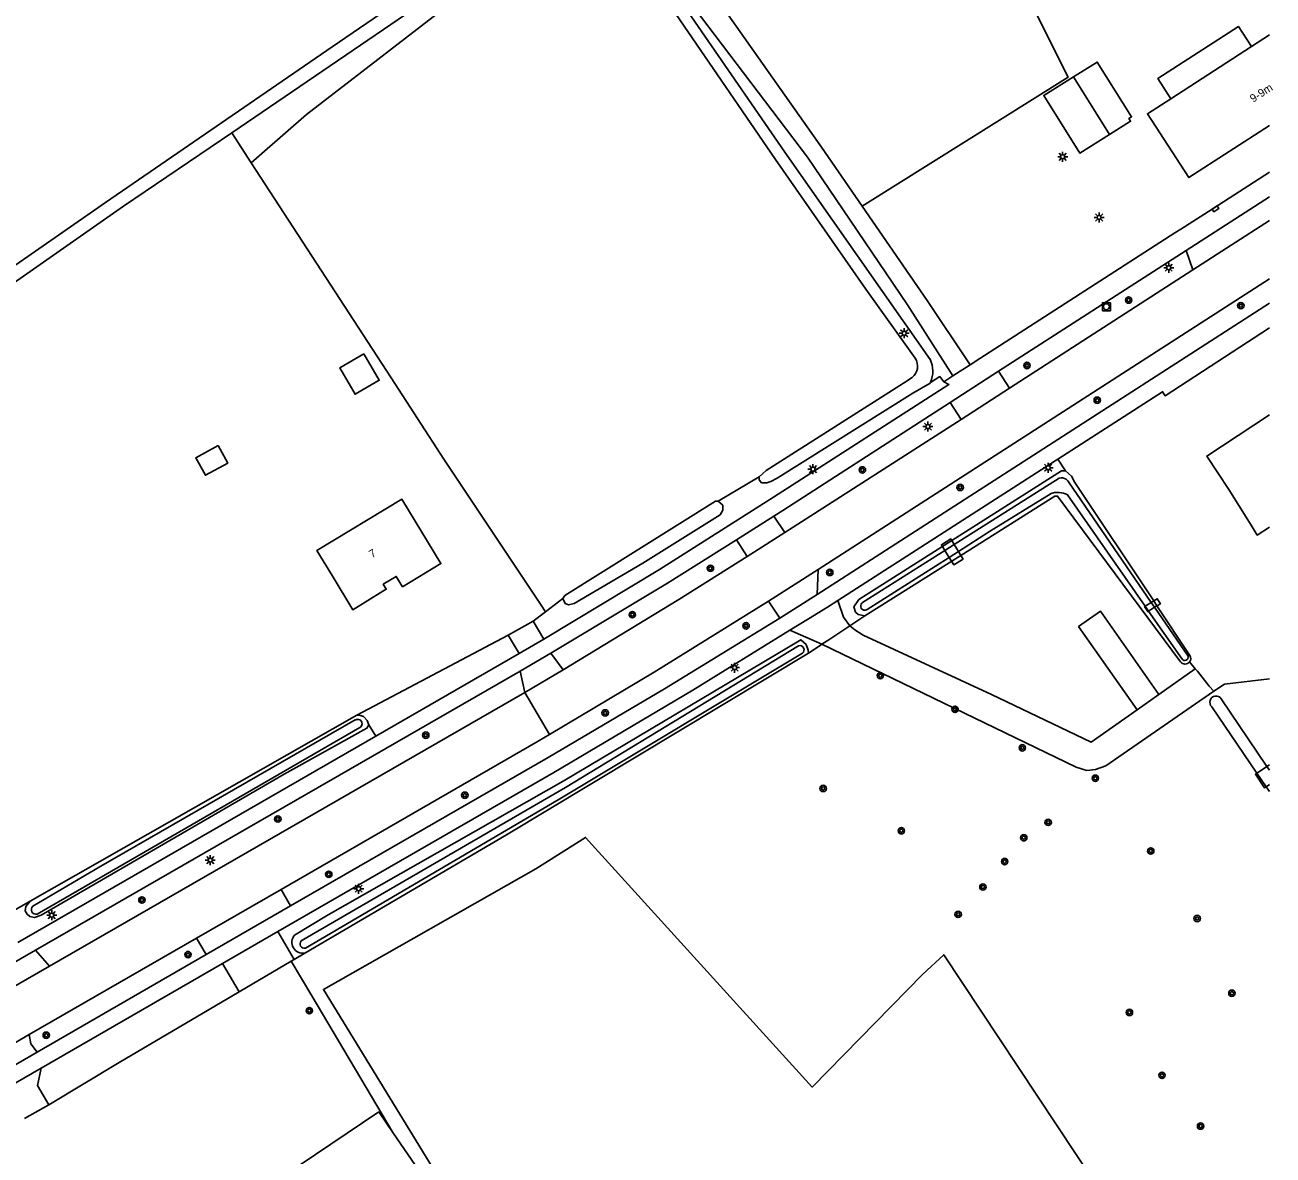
# Model space of a CAD drawing. Extents: x 137000 to 140001, y 403500 to 406000.
# Drawn here: x 139844.4 to 140000.4, y 404057.8 to 404199.1 of the extents above; entities that cross this region are included whole.
import ezdxf

# ---------------------------------------------------------------- set-up
doc = ezdxf.new("R2010")
doc.units = 0
for name, color, linetype in [('gg-afsc-erfafscheiding', 7, 'Continuous'), ('gg-afsc-hekwerk', 7, 'Continuous'), ('gg-anno-huisnummerreeks BGT', 7, 'Continuous'), ('gg-bbg-bijgebouw', 7, 'Continuous'), ('gg-bbg-hoofdgebouw', 7, 'Continuous'), ('gg-bbg-luifel en loopbrug', 7, 'Continuous'), ('gg-bbg-overig bouwwerk', 7, 'Continuous'), ('gg-knt-bronhoudergrens', 7, 'Continuous'), ('gg-knt-verharding', 7, 'Continuous'), ('gg-knt-verharding nz', 7, 'Continuous'), ('gg-kntw-bovenkant insteek waterloop', 7, 'Continuous'), ('gg-kntw-waterlijn', 7, 'Continuous'), ('gg-kwrk-kunstwerk niveau 01', 7, 'Continuous'), ('gt-grn-groengrens', 7, 'Continuous'), ('gt-grn-weggrens', 7, 'Continuous'), ('gt-symb-boom', 7, 'Continuous'), ('gt-symb-kolk', 7, 'Continuous'), ('gt-symb-lichtmast', 7, 'Continuous'), ('gt-symb-rioolschacht', 7, 'Continuous')]:
    doc.layers.add(name, color=color, linetype=linetype)

# ---------------------------------------------------------------- blocks, each defined once
blk = doc.blocks.new('gt0-BOOM')
at = {"layer": 'gt-symb-boom'}
for radius in [0.4, 0.2]:
    blk.add_circle((0, 0), radius, dxfattribs=at)
blk = doc.blocks.new('gt0-LMAST')
at = {"layer": 'gt-symb-lichtmast'}
for p, q in [((-0.18, 0.17), (-0.45, 0.44)), ((-0.01, 0.25), (-0.01, 0.62)), ((0.17, 0.17), (0.44, 0.44)), ((-0.26, 0), (-0.63, 0)), ((-0.18, -0.18), (-0.45, -0.45)), ((-0.01, -0.25), (-0.01, -0.63)), ((0.44, -0.45), (0.17, -0.18)), ((0.24, 0), (0.62, 0))]:
    blk.add_line(p, q, dxfattribs=at)
blk.add_circle((-0.01, 0), 0.25, dxfattribs=at)
blk = doc.blocks.new('gt0-RS')
at = {"layer": 'gt-symb-rioolschacht'}
blk.add_lwpolyline([(-0.5, -0.5), (0.5, -0.5), (0.5, 0.5), (-0.5, 0.5)], close=True, dxfattribs=at)
blk.add_circle((0, 0), 0.375, dxfattribs=at)
blk = doc.blocks.new('gt0-KOLK')
at = {"layer": 'gt-symb-kolk'}
blk.add_lwpolyline([(0, 0), (0.37, 0), (0.37, 0.4), (-0.38, 0.4), (-0.38, 0), (0, 0)], dxfattribs=at)

msp = doc.modelspace()

# ---------------------------------------------------------------- linework, layer by layer
at = {"layer": 'gg-afsc-erfafscheiding'}
for p, q in [((139870.28, 404185.61), (139872.71, 404181.86)), ((139973.54, 404144.82), (139974.5, 404143.33)), ((139985.52, 404127.09), (139985.93, 404126.47)), ((139985.93, 404126.47), (139990.05, 404120.27)), ((139907.98, 404124.53), (139909.49, 404125.71)), ((139885.94, 404112.81), (139904.84, 404122.82)), ((139845.1, 404089.56), (139885.94, 404112.81)), ((139841.07, 404087.26), (139845.1, 404089.56))]:
    msp.add_line(p, q, dxfattribs=at)
for points in [[(139974.5, 404143.33), (139975.26, 404142.69), (139975.67, 404141.9), (139985.52, 404127.09)], [(139877.72, 404082.05), (139880.3, 404077.7), (139890.43, 404060.62)]]:
    msp.add_lwpolyline(points, dxfattribs=at)
msp.add_arc((139989.44, 404119.9), 0.72, 321.2636, 31.3937, dxfattribs=at)
at = {"layer": 'gg-afsc-hekwerk'}
for p, q in [((139885.94, 404112.81), (139845.1, 404089.56)), ((139845.1, 404089.56), (139841.07, 404087.26)), ((139871.2, 404078.22), (139856.22, 404069.39)), ((139847.42, 404064.1), (139856.22, 404069.39))]:
    msp.add_line(p, q, dxfattribs=at)
at = {"layer": 'gg-bbg-bijgebouw'}
msp.add_line((139890.43, 404060.62), (139888.66, 404063.2), dxfattribs=at)
for points in [[(139888.66, 404063.2), (139860.82, 404044.45), (139872, 404028.17), (139898.92, 404046.3)], [(139898.92, 404046.3), (139899.84, 404046.92), (139890.43, 404060.62)]]:
    msp.add_lwpolyline(points, dxfattribs=at)
at = {"layer": 'gg-bbg-hoofdgebouw'}
for q in [(140000, 404197.85), (139987.65, 404189.86)]:
    msp.add_line((139997.73, 404196.38), q, dxfattribs=at)
for points in [[(139987.65, 404189.86), (139984.74, 404187.98), (139989.93, 404180), (140000, 404186.49)], [(140000, 404150.35), (139992.14, 404145.18), (139994.89, 404141), (139997.69, 404136.53), (139998.46, 404135.31), (140000, 404136.32)], [(139889.19, 404128.28), (139889.6, 404128.53), (139889.22, 404129.16), (139890.85, 404130.14), (139891.63, 404128.85), (139896.42, 404131.75), (139891.55, 404139.79), (139880.92, 404133.37), (139882.82, 404130.25), (139885.42, 404125.98), (139889.19, 404128.28)]]:
    msp.add_lwpolyline(points, dxfattribs=at)
at = {"layer": 'gg-bbg-luifel en loopbrug'}
msp.add_line((139979.98, 404185.38), (139975.49, 404192.58), dxfattribs=at)
for points in [[(139997.73, 404196.38), (139996.1, 404198.9), (139986.02, 404192.38), (139987.65, 404189.86)], [(139979.98, 404185.38), (139982.63, 404187.03), (139982.42, 404187.37), (139982.76, 404187.58), (139978.47, 404194.44), (139975.49, 404192.58)], [(139975.49, 404192.58), (139971.77, 404190.26), (139976.27, 404183.06), (139979.98, 404185.38)]]:
    msp.add_lwpolyline(points, dxfattribs=at)
at = {"layer": 'gg-bbg-overig bouwwerk'}
for points in [[(139886.81, 404157.95), (139883.79, 404156.2), (139885.7, 404152.91), (139888.72, 404154.66), (139886.81, 404157.95)], [(139868.59, 404146.51), (139865.79, 404144.98), (139866.99, 404142.78), (139869.79, 404144.31), (139868.59, 404146.51)]]:
    msp.add_lwpolyline(points, dxfattribs=at)
at = {"layer": 'gg-knt-bronhoudergrens'}
for points in [[(139949.08, 404176.44), (139974.82, 404192.53), (139967.8, 404206.65), (139975.35, 404211.27), (139975.52, 404212.67), (139977.9, 404214.5), (139981.43, 404217.7), (139983.63, 404220.66), (139984.38, 404222.22), (139987.69, 404224.46), (139993.63, 404227.8), (139995.73, 404224.77), (140000, 404226.86)], [(139908.29, 404093.58), (139914.51, 404097.52), (139942.82, 404066.32), (139956.67, 404080.42), (139959.27, 404082.86), (139970.91, 404065.29), (139993.05, 404031.94)], [(139932.29, 403995.97), (139881.75, 404078.52), (139908.29, 404093.58)]]:
    msp.add_lwpolyline(points, dxfattribs=at)
at = {"layer": 'gg-knt-verharding'}
for p, q in [((139989.58, 404170.9), (140000, 404177.61)), ((139989.58, 404170.9), (139966.14, 404155.79)), ((139990.43, 404168.46), (139989.58, 404170.9)), ((139990.43, 404168.46), (139967.51, 404153.68)), ((139943.59, 404131.02), (140000, 404167.36)), ((139943.45, 404127.88), (140000, 404164.32)), ((139962.57, 404156.59), (139960.43, 404155.22)), ((139959.27, 404154.47), (139960.43, 404155.22)), ((139960.09, 404151.88), (139966.14, 404155.79)), ((139966.14, 404155.79), (139967.51, 404153.68)), ((139961.45, 404149.77), (139960.09, 404151.88)), ((139938.05, 404137.69), (139933.36, 404134.73)), ((139939.43, 404135.63), (139938.05, 404137.69)), ((139934.72, 404132.65), (139933.36, 404134.73)), ((139943.59, 404131.02), (139943.45, 404127.88)), ((139938.78, 404124.94), (139943.45, 404127.88)), ((139937.38, 404127.05), (139938.78, 404124.94)), ((139904.84, 404122.82), (139907.98, 404124.53)), ((139907.98, 404124.53), (139909.3, 404122.31)), ((139944.04, 404121.66), (139940.04, 404123.41)), ((139904.84, 404122.82), (139906.19, 404120.5)), ((139906.19, 404120.5), (139909.3, 404122.31)), ((139888.29, 404110.18), (139906.19, 404120.5)), ((139910.17, 404120.54), (139906.33, 404118.3)), ((139911.7, 404118.47), (139910.17, 404120.54)), ((139990.72, 404118.6), (139986.17, 404115.4)), ((139990, 404119.45), (139990.72, 404118.6)), ((139845.77, 404083.43), (139906.33, 404118.3)), ((139906.9, 404115.64), (139906.33, 404118.3)), ((139906.9, 404115.64), (139847.49, 404081.43)), ((139986.17, 404115.4), (139983.44, 404113.48)), ((139888.29, 404110.18), (139843.56, 404084.39)), ((139865.9, 404084.93), (139876.46, 404091.02)), ((139876.46, 404091.02), (139877.65, 404088.96)), ((139867.1, 404082.87), (139877.65, 404088.96)), ((139876.04, 404085.75), (139869.12, 404081.77)), ((139878.08, 404082.27), (139876.04, 404085.75)), ((139844.98, 404072.87), (139865.9, 404084.93)), ((139865.9, 404084.93), (139867.1, 404082.87)), ((139845.77, 404083.43), (139836.05, 404077.83)), ((139847.49, 404081.43), (139845.77, 404083.43)), ((139845.95, 404070.67), (139867.1, 404082.87)), ((139869.12, 404081.77), (139846.46, 404068.69)), ((139869.12, 404081.77), (139871.2, 404078.22)), ((139871.2, 404078.22), (139877.72, 404082.05)), ((139840.31, 404067.41), (139845.95, 404070.67)), ((139846.46, 404068.69), (139841.28, 404065.7)), ((139847.42, 404064.1), (139844.4, 404062.39))]:
    msp.add_line(p, q, dxfattribs=at)
for points in [[(139909.49, 404125.71), (139908.95, 404126.57), (139896.79, 404144.8), (139890.2, 404154.98), (139872.71, 404181.86)], [(139962.57, 404156.59), (139963.79, 404157.38), (139988.18, 404173.08), (139988.92, 404173.55), (139992.35, 404175.76), (140000, 404180.68)], [(139949.08, 404176.44), (139957.22, 404164.65), (139962.57, 404156.59)], [(139973.54, 404144.82), (139986.63, 404153.23), (139986.95, 404152.73), (140000, 404161.2)], [(139959.27, 404154.47), (139959.92, 404154.14), (139938.01, 404140.03), (139923.76, 404131.01), (139909.3, 404122.31)], [(139938.05, 404137.69), (139939.17, 404138.39), (139960.09, 404151.88)], [(139939.43, 404135.63), (139940.46, 404136.28), (139961.45, 404149.77)], [(139973.54, 404144.82), (139973.2, 404144.6), (139946.04, 404127.14)], [(139933.36, 404134.73), (139924.76, 404129.31), (139910.17, 404120.54)], [(139934.72, 404132.65), (139926.16, 404127.24), (139911.7, 404118.47)], [(139910.02, 404110.4), (139923.07, 404118.18), (139937.38, 404127.05)], [(139940.04, 404123.41), (139942.39, 404124.86), (139944.76, 404126.32), (139946.04, 404127.14)], [(139947.54, 404123.97), (139946.76, 404125.07), (139946.04, 404127.14)], [(139877.65, 404088.96), (139909.82, 404107.52), (139924.38, 404116.11), (139938.78, 404124.94)], [(139986.17, 404115.4), (139978.87, 404125.79), (139976.13, 404123.87), (139983.44, 404113.48)], [(139940.04, 404123.41), (139927.91, 404115.93), (139910.53, 404105.65), (139876.04, 404085.75)], [(139944.04, 404121.66), (139945.02, 404122.3), (139947.54, 404123.97)], [(139947.54, 404123.97), (139948.17, 404123.46), (139949.19, 404122.78), (139965.24, 404115.39), (139977.7, 404109.44), (139983.44, 404113.48)], [(139993.03, 404115.82), (139981.18, 404107.59), (139979.54, 404106.47), (139978.25, 404106.02), (139977.17, 404105.89), (139975.82, 404106.32), (139944.04, 404121.66)], [(139990.72, 404118.6), (139990.98, 404118.3), (139992.47, 404116.41), (139993.03, 404115.82)], [(139993.03, 404115.82), (139994.36, 404116.67), (140000, 404117.35)], [(139876.46, 404091.02), (139908.6, 404109.55), (139910.02, 404110.4)], [(139877.72, 404082.05), (139878.08, 404082.26), (139878.08, 404082.27)], [(139845.95, 404070.67), (139845.18, 404071.72), (139844.98, 404072.87)], [(139846.46, 404068.69), (139846.01, 404066.51), (139847.42, 404064.1)]]:
    msp.add_lwpolyline(points, dxfattribs=at)
at = {"layer": 'gg-knt-verharding nz'}
for p, q in [((139990.43, 404168.46), (140000, 404174.63)), ((139967.51, 404153.68), (139961.45, 404149.77)), ((139934.72, 404132.65), (139939.43, 404135.63)), ((139937.38, 404127.05), (139943.59, 404131.02)), ((139911.7, 404118.47), (139906.9, 404115.64)), ((139847.49, 404081.43), (139837.32, 404075.57)), ((139844.98, 404072.87), (139838.86, 404069.34))]:
    msp.add_line(p, q, dxfattribs=at)
at = {"layer": 'gg-kntw-bovenkant insteek waterloop'}
for p, q in [((139960.59, 404134.12), (139959.43, 404133.39)), ((139959.95, 404132.52), (139961.11, 404133.26)), ((139984.45, 404126.43), (139984.87, 404125.82)), ((139985.63, 404126.28), (139985.21, 404126.9)), ((139992.77, 404113.83), (139998.43, 404105.54)), ((139993.96, 404114.86), (139999.68, 404106.38)), ((139845.96, 404087.93), (139886.3, 404111.24)), ((139999.68, 404106.38), (140000, 404105.91)), ((139998.43, 404105.54), (139999.58, 404103.85)), ((139999.58, 404103.85), (140000, 404103.24))]:
    msp.add_line(p, q, dxfattribs=at)
for points in [[(139777.24, 404123.6), (139796.02, 404136.4), (139822.77, 404154.86), (139854.51, 404176.9), (139882.82, 404196.33), (139904.39, 404211.07), (139912.76, 404216.98)], [(139957.59, 404157.27), (139939.42, 404183.18), (139926.09, 404202.55), (139915.74, 404217.27)], [(139870.28, 404185.61), (139906.27, 404210.13), (139912.64, 404214.82)], [(139915.67, 404214.61), (139922.12, 404205.83), (139938.26, 404182.24), (139949.55, 404166.06), (139955.71, 404157.42)], [(139778.07, 404121.99), (139799.67, 404136.56), (139827.67, 404156.11), (139856.76, 404176.41), (139870.28, 404185.61)], [(139955.32, 404155.01), (139954.25, 404154.31), (139937.1, 404143.39), (139936.21, 404142.61)], [(139936.21, 404142.61), (139936.21, 404142.21), (139936.5, 404141.84), (139937.15, 404141.83), (139937.66, 404142), (139938.46, 404142.43), (139955.42, 404153.03), (139957.56, 404154.28), (139957.62, 404154.4)], [(139960.59, 404134.12), (139973.72, 404142.44), (139973.94, 404142.47), (139974.17, 404142.45), (139974.38, 404142.39), (139974.58, 404142.28), (139974.75, 404142.14), (139974.89, 404141.96), (139985.21, 404126.9)], [(139961.11, 404133.26), (139965, 404135.74), (139972.71, 404140.51), (139973.14, 404140.62), (139973.42, 404140.65), (139973.7, 404140.64), (139973.97, 404140.61), (139974.24, 404140.56), (139974.51, 404140.47), (139974.76, 404140.36), (139984.45, 404126.43)], [(139911.65, 404127.4), (139911.93, 404127.77), (139930.77, 404139.57), (139931.1, 404139.56)], [(139911.65, 404127.4), (139911.98, 404126.75), (139912.36, 404126.58), (139913.1, 404126.74), (139921.65, 404131.8), (139931.34, 404137.86), (139931.67, 404138.43), (139931.65, 404139.04), (139931.1, 404139.56)], [(139959.43, 404133.39), (139949.12, 404126.87), (139949.04, 404126.79), (139948.94, 404126.66), (139948.9, 404126.5), (139948.9, 404126.34), (139948.96, 404126.18), (139949.05, 404126.06), (139949.06, 404126.05), (139949.2, 404125.96), (139949.3, 404125.92), (139949.47, 404125.91), (139949.63, 404125.95), (139949.72, 404126.01), (139959.95, 404132.52)], [(139984.87, 404125.82), (139989.06, 404119.8), (139989.15, 404119.71), (139989.27, 404119.65), (139989.41, 404119.63), (139989.58, 404119.67), (139989.73, 404119.78), (139989.8, 404119.9), (139989.83, 404120.03), (139989.82, 404120.16), (139985.63, 404126.28)], [(139942.36, 404120.55), (139942.33, 404120.93), (139942.09, 404121.62), (139941.4, 404122.23), (139911.72, 404104.53), (139882.35, 404087.84), (139878.15, 404085.31)], [(139879.44, 404083.06), (139904.63, 404097.85), (139942.36, 404120.55)], [(139845.41, 404088.91), (139853.94, 404093.93), (139885.72, 404112.2)]]:
    msp.add_lwpolyline(points, dxfattribs=at)
for centre, radius, start, end in [((139954.18, 404156.43), 1.82, 308.6086, 33.0069), ((139954.41, 404155.81), 3.5, 336.3307, 24.8264), ((139993.32, 404114.4), 0.788, 35.5911, 226.245), ((139886.02, 404111.72), 0.557, 300.9127, 121.9318), ((139845.82, 404088.5), 0.585, 135.0381, 283.5554), ((139879.18, 404084.4), 1.37, 138.8045, 280.8773)]:
    msp.add_arc(centre, radius, start, end, dxfattribs=at)
at = {"layer": 'gg-kntw-waterlijn'}
for points in [[(139941.14, 404121.48), (139912.02, 404103.76), (139878.97, 404084.58)], [(139941.62, 404120.53), (139911.07, 404102.23), (139879.49, 404083.68)]]:
    msp.add_lwpolyline(points, dxfattribs=at)
for centre, radius, start, end in [((139941.27, 404120.95), 0.549, 310.2963, 104.1278), ((139879.37, 404084.21), 0.546, 137.6685, 282.5038)]:
    msp.add_arc(centre, radius, start, end, dxfattribs=at)
at = {"layer": 'gg-kwrk-kunstwerk niveau 01'}
for p, q in [((139960.59, 404134.12), (139960.28, 404134.63)), ((139961.11, 404133.26), (139961.41, 404132.77)), ((139985.21, 404126.9), (139985.52, 404127.09)), ((139985.63, 404126.28), (139985.93, 404126.47)), ((139999.68, 404106.38), (140000, 404106.59)), ((139999.58, 404103.85), (140000, 404104.13))]:
    msp.add_line(p, q, dxfattribs=at)
for points in [[(139959.43, 404133.39), (139959.12, 404133.89), (139958.98, 404134.11), (139960.16, 404134.83), (139960.28, 404134.63)], [(139960.59, 404134.12), (139960.91, 404133.59), (139961.11, 404133.26)], [(139959.43, 404133.39), (139959.75, 404132.85), (139959.95, 404132.52)], [(139959.95, 404132.52), (139960.25, 404132.04), (139960.52, 404131.6), (139961.69, 404132.32), (139961.41, 404132.77)], [(139984.45, 404126.43), (139984.38, 404126.38), (139984.77, 404125.75), (139984.87, 404125.82)], [(139984.45, 404126.43), (139984.67, 404126.56), (139985.21, 404126.9)], [(139984.87, 404125.82), (139985.1, 404125.96), (139985.63, 404126.28)], [(139985.52, 404127.09), (139985.96, 404127.36), (139986.35, 404126.73), (139985.93, 404126.47)], [(139998.43, 404105.54), (139999.01, 404105.92), (139999.68, 404106.38)], [(139998.43, 404105.54), (139998.24, 404105.41), (139999.38, 404103.71), (139999.58, 404103.85)]]:
    msp.add_lwpolyline(points, dxfattribs=at)
at = {"layer": 'gt-grn-groengrens'}
for p, q in [((139931.1, 404139.56), (139936.21, 404142.61)), ((139949.41, 404125.2), (139961.41, 404132.77)), ((139911.65, 404127.4), (139909.49, 404125.71)), ((139947.54, 404123.97), (139949.41, 404125.2)), ((139878.08, 404082.27), (139879.44, 404083.06))]:
    msp.add_line(p, q, dxfattribs=at)
for points in [[(139949.08, 404176.44), (139944, 404183.79), (139930.56, 404202.94), (139917.8, 404221.74), (139900.69, 404247.1), (139894.41, 404255.93), (139872.55, 404286.31), (139866.9, 404295.65), (139859.76, 404305.63), (139845.82, 404324.3), (139838.37, 404332.94), (139832.19, 404339.57), (139831.5, 404340.22)], [(139960.43, 404155.22), (139954.76, 404164.1), (139942.24, 404182.53), (139928.1, 404201.23), (139915.33, 404220.04), (139898.64, 404244.81), (139896.29, 404248.12)], [(139915.21, 404214.92), (139907.83, 404209.69), (139879.64, 404187.89), (139874.04, 404183.02), (139872.71, 404181.86)], [(139961.41, 404132.77), (139973.15, 404140.18), (139973.51, 404140.19), (139988.87, 404119.45)], [(139942.36, 404120.55), (139943.82, 404121.51), (139944.04, 404121.66)]]:
    msp.add_lwpolyline(points, dxfattribs=at)
msp.add_arc((139989.43, 404119.9), 0.722, 218.2669, 321.4294, dxfattribs=at)
at = {"layer": 'gt-grn-weggrens'}
for p, q in [((139906.9, 404115.64), (139910.02, 404110.4)), ((139888.29, 404110.18), (139887.4, 404111.61))]:
    msp.add_line(p, q, dxfattribs=at)
for points in [[(139957.62, 404154.4), (139958.77, 404155.12), (139959.27, 404154.47)], [(139974.5, 404143.33), (139973.98, 404143.35), (139960.28, 404134.63)], [(139960.28, 404134.63), (139948.68, 404127.24), (139948.04, 404126.35), (139948.24, 404125.69), (139948.57, 404125.38), (139949.41, 404125.2)], [(139885.94, 404112.81), (139886.36, 404112.76), (139886.75, 404112.63), (139887.22, 404112.14), (139887.4, 404111.61)], [(139845.1, 404089.56), (139844.57, 404088.87), (139844.48, 404088.35), (139844.71, 404087.92), (139845.07, 404087.62), (139845.65, 404087.51), (139846.47, 404087.78), (139876.83, 404105.43), (139887.18, 404111.17), (139887.4, 404111.61)]]:
    msp.add_lwpolyline(points, dxfattribs=at)

# ---------------------------------------------------------------- block references
at = {"layer": 'gt-symb-boom'}
for p in [(139982.39, 404164.68), (139996.41, 404163.99), (139969.68, 404156.51), (139978.46, 404152.17), (139949.11, 404143.46), (139961.33, 404141.27), (139930.12, 404131.16), (139945.03, 404130.64), (139920.35, 404125.36), (139934.57, 404123.97), (139951.35, 404117.74), (139960.69, 404113.53), (139916.96, 404113.08), (139894.54, 404110.3), (139969.1, 404108.72), (139978.23, 404104.92), (139899.42, 404102.79), (139944.21, 404103.64), (139876.05, 404099.82), (139972.33, 404099.4), (139953.98, 404098.35), (139969.28, 404097.48), (139985.15, 404095.82), (139966.89, 404094.5), (139882.41, 404092.91), (139964.17, 404091.32), (139859.06, 404089.7), (139961.08, 404087.9), (139990.95, 404087.38), (139864.82, 404082.87), (139995.29, 404078.04), (139879.98, 404075.86), (139982.49, 404075.64), (139847.1, 404072.79), (139986.56, 404067.78), (139991.38, 404061.43)]:
    msp.add_blockref('gt0-BOOM', p, dxfattribs=at)
at = {"layer": 'gt-symb-kolk', "rotation": -147.2366490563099}
msp.add_blockref('gt0-KOLK', (139993.12, 404176.26), dxfattribs=at)
at = {"layer": 'gt-symb-lichtmast'}
for p in [(139974.15, 404182.6), (139978.71, 404175.01), (139987.4, 404168.73), (139954.34, 404160.54), (139957.31, 404148.87), (139942.94, 404143.55), (139972.34, 404143.73), (139933.15, 404118.74), (139867.61, 404094.68), (139886.16, 404091.11), (139847.79, 404087.8)]:
    msp.add_blockref('gt0-LMAST', p, dxfattribs=at)
at = {"layer": 'gt-symb-rioolschacht'}
msp.add_blockref('gt0-RS', (139979.6, 404163.86), dxfattribs=at)

# ---------------------------------------------------------------- texts
at = {"layer": 'gg-anno-huisnummerreeks BGT'}
for s, rotation, p in [('9-9m', 32.8, (139997.95, 404189.34)), ('7', 31, (139887.82, 404132.4))]:
    msp.add_text(s, height=1, rotation=rotation, dxfattribs=at).set_placement(p)

doc.saveas('drawing.dxf')
